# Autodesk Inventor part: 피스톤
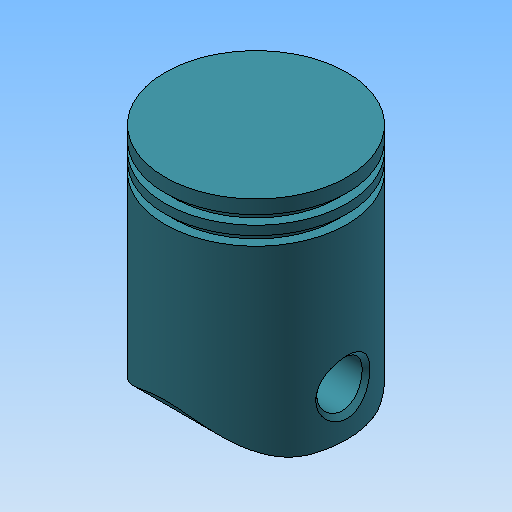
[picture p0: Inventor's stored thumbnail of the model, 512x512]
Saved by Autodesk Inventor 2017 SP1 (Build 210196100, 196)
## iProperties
Created: 2017-05
Part Number: 피스톤
Material: 알루미늄 6061
Document SubType Name: Modeling
Designer: mduedu
Density: 2.71 g/cm^3
Mass: 87.6985 g
Surface Area: 150.47 cm^2
Volume: 32.3611 cm^3
Appearance: 커뎃 파란색
Author: mduedu
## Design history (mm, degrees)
sketch "스케치1"
  geometry: L1 (0, 0)-(20, 0); L2 (20, -50)-(15, -50); L3 (15, -50)-(15, -5); L4 (15, -5)-(0, -5); L5 (0, -5)-(0, 0); L6 (20, -3)-(18, -3); L7 (18, -3)-(18, -5); L8 (18, -5)-(20, -5); L9 (20, -7)-(18, -7); L10 (18, -7)-(18, -9); L11 (18, -9)-(20, -9); L12 (20, 0)-(20, -3); L13 (20, -5)-(20, -7); L14 (20, -9)-(20, -50); L15 (0, -60)-(0, 10) reference
  constraints: 28 end point, 10 parallel, 5 perpendicular, 4 collinear, 3 horizontal
  dimensions: "d0" = 20 distance of L1.start L1.end; "d1" = 2 distance of L6.start L6.end; "d2" = 2 distance of L6.end L7.end; "d3" = 2 distance of L8.end L9.start; "d4" = 3 distance of L1.end L6.start; "d5" = 5 distance of L2.start L2.end; "d6" = 50 distance between parallel lines of L1 L2; "d7" = 5 distance of L4.end L1.start
revolve "회전1" sketch "스케치1" stored, may be unused: angle "d8" = 90 deg
fillet "모깎기1" dims "d9" = 1
sketch "스케치2"
  geometry: L1 (-50, 15)-(-50, -15) reference; C1 r 10 at (-40, 0); 1 further point
  constraints: 1 centre point, 1 horizontal alignment
  dimensions: "d10" = 20 diameter of C1; "d11" = 10 distance from line of C1.centre L1
extrude "돌출1" join sketch "스케치2" stored distance "d12" = 10; taper "d13" = 0 deg
sketch "스케치3"
  geometry: L1 (0, -20)-(-3, -20) reference; L2 (-3, -20)-(-3, -18) reference; L3 (-3, -18)-(-5, -18) reference; L4 (-5, -18)-(-5, -20) reference; L5 (-5, -20)-(-7, -20) reference; L6 (-7, -20)-(-7, -18) reference; L7 (-7, -18)-(-9, -18) reference; L8 (-9, -18)-(-9, -20) reference; L9 (-9, -20)-(-50, -20) reference; L10 (-50, -20)-(-50, -15) reference; L11 (-50, -15)-(-6, -15) reference; L12 (-5, -14)-(-5, 14) reference; L13 (-6, 15)-(-50, 15) reference; L14 (-50, 15)-(-50, 20) reference; L15 (-50, 20)-(-9, 20) reference; L16 (-9, 20)-(-9, 18) reference; L17 (-9, 18)-(-7, 18) reference; L18 (-7, 18)-(-7, 20) reference; L19 (-7, 20)-(-5, 20) reference; L20 (-5, 20)-(-5, 18) reference; L21 (-5, 18)-(-3, 18) reference; L22 (-3, 18)-(-3, 20) reference; L23 (-3, 20)-(0, 20) reference; L24 (0, 20)-(0, -20) reference; C1 r 10 at (-40, 0) reference; C2 r 5 at (-40, 0); A1 r 1 centre (-6, -14) between (-6, -15) and (-5, -14) reference; A2 r 1 centre (-6, 14) between (-5, 14) and (-6, 15) reference; 1 further point
  constraints: 1 centre point, 1 coincident
  dimensions: "d15" = 10 diameter of C2
extrude "돌출2" cut sketch "스케치3" stored distance "d16" = 10; taper "d17" = 0 deg
sketch "스케치4"
  geometry: L1 (15, -50)-(-15, -50) reference; L2 (-15, -50)-(-20, -50) reference; L3 (-20, -50)-(-20, -45) reference; L4 (20, -45)-(20, -50) reference; L5 (20, -50)-(15, -50) reference; L6 (-15, -30)-(15, -30) reference; L7 (15, -30)-(15, -6) reference; L8 (14, -5)-(-14, -5) reference; L9 (-15, -6)-(-15, -30) reference; L10 (-20, -3)-(-20, 0) reference; L11 (-20, 0)-(20, 0) reference; L12 (20, 0)-(20, -3) reference; L13 (20, -3)-(18, -3) reference; L14 (18, -3)-(18, -5) reference; L15 (18, -5)-(20, -5) reference; L16 (20, -5)-(20, -7) reference; L17 (20, -7)-(18, -7) reference; L18 (18, -7)-(18, -9) reference; L19 (18, -9)-(20, -9) reference; L20 (-20, -9)-(-18, -9) reference; L21 (-18, -9)-(-18, -7) reference; L22 (-18, -7)-(-20, -7) reference; L23 (-20, -7)-(-20, -5) reference; L24 (-20, -5)-(-18, -5) reference; L25 (-18, -5)-(-18, -3) reference; L26 (-18, -3)-(-20, -3) reference; L27 (0, 0)-(0, -50); L28 (-5.698, -50)-(-5, -30); L29 (5.698, -50)-(5, -30); L30 (-5, -30)-(5, -30); L31 (-5.698, -50)-(5.698, -50); L32 (-20, -45)-(20, -45) reference; L33 (20, -9)-(20, -35) reference; L34 (20, -35)-(-20, -35) reference; L35 (-20, -35)-(-20, -9) reference; A1 r 1 centre (14, -6) between (15, -6) and (14, -5) reference; A2 r 1 centre (-14, -6) between (-14, -5) and (-15, -6) reference
  constraints: 10 end point, 2 point on line, 2 symmetric about line, 1 midpoint, 1 parallel, 1 perpendicular
  dimensions: "d18" = 2 deg angle of L27 L28; "d19" = 5 distance from line of L27 L28.end
extrude "돌출3" cut sketch "스케치4" stored distance "d20" = 20; taper "d21" = 0 deg
chamfer "모따기1" distance "d22" = 1; stored, may be unused: second distance "d23" = 2, angle "d24" = 45 deg
sketch "스케치5"
  geometry: L1 (-50, 0)-(-50, -15) reference; L2 (-50, 15)-(-50, 0) reference; L3 (-9, 20)-(-50, 20) reference; L4 (-50, 20)-(-50, -20) reference; L5 (-9, -20)-(-50, -20) reference; L6 (-42.483, -20)-(-50, -20); L7 (-50, -20)-(-50, -7); L8 (-42.483, 20)-(-50, 20); L9 (-50, 20)-(-50, 7); A1 r 15 centre (-35, 7) between (-42.483, 20) and (-50, 7); A2 r 15 centre (-35, -7) between (-42.483, -20) and (-50, -7); 1 further point
  constraints: 8 end point, 4 point on circle, 4 point on line, 2 centre point, 2 tangent, 1 collinear, 1 equal radius, 1 perpendicular
  dimensions: "d25" = 30 diameter of A1; "d26" = 7 vertical distance of A2.centre point (0, 0); "d27" = 7 vertical distance of point (0, 0) A1.centre (= d26)
extrude "돌출4" cut sketch "스케치5" stored distance "d28" = 20; taper "d29" = 0 deg
node "솔리드1"
node "절단 모서리 투영1"
node "절단 모서리 투영2"
